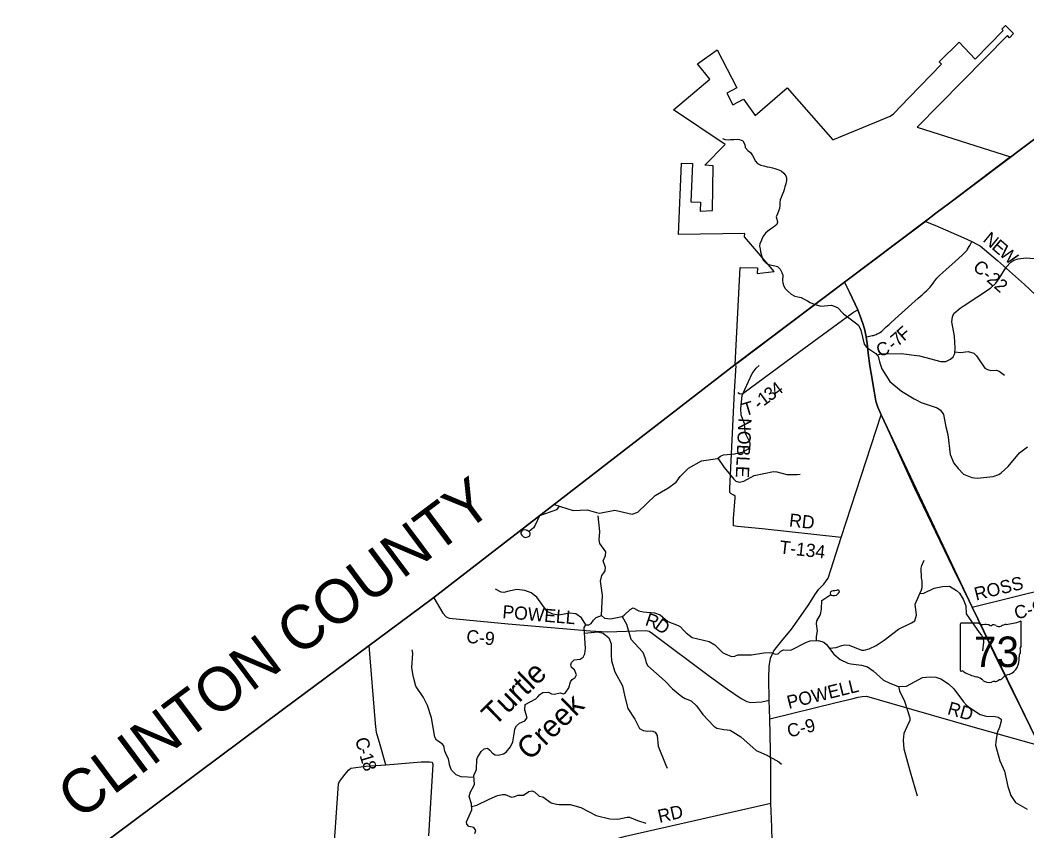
# Model space of a CAD drawing. Extents: x 1525783 to 1900577, y 218250 to 627376.
# Drawn here: x 1612574 to 1635582, y 470168 to 488683 of the extents above; entities that cross this region are included whole.
import ezdxf

# ---------------------------------------------------------------- set-up
doc = ezdxf.new("R2010")
doc.units = 0
for name, color, linetype in [('GM_X_Adjacent_County', 7, 'Continuous'), ('GM_X_Adjacent_County_Text', 7, 'Continuous'), ('GM_X_Corporation', 7, 'Continuous'), ('GM_X_County', 7, 'Continuous'), ('GM_X_County_Road', 7, 'Continuous'), ('GM_X_County_Road_Text', 7, 'Continuous'), ('GM_X_Minor_Lake', 7, 'Continuous'), ('GM_X_Minor_River', 7, 'Continuous'), ('GM_X_Minor_River_Text', 7, 'Continuous'), ('GM_X_State_Location', 7, 'Continuous'), ('GM_X_State_Route', 7, 'Continuous'), ('GM_X_State_Shield', 7, 'Continuous'), ('GM_X_Township', 7, 'Continuous'), ('GM_X_Township_Road', 7, 'Continuous'), ('GM_X_Township_Road_Text', 7, 'Continuous')]:
    doc.layers.add(name, color=color, linetype=linetype)

msp = doc.modelspace()

# ---------------------------------------------------------------- linework, layer by layer
at = {"layer": 'GM_X_Adjacent_County'}
msp.add_lwpolyline([(1655741, 500852), (1648788, 495779), (1648023, 495203), (1647133, 494533), (1640676, 489672), (1638042, 487688), (1635644, 485883), (1633819, 484508), (1633505, 484272), (1633248, 484078), (1631413, 482696), (1628958, 480847), (1628919, 480818), (1621997, 475474), (1621966, 475451), (1620523, 474378), (1618604, 472952), (1614700, 470050), (1612987, 468763), (1608261, 465210)], dxfattribs=at)
at = {"layer": 'GM_X_Corporation'}
msp.add_lwpolyline([(1627691, 485418), (1627940, 485406), (1627901, 484537), (1628121, 484528), (1628112, 484317), (1628398, 484333), (1628411, 485354), (1628219, 485374), (1628686, 485841), (1627505, 486638), (1628338, 487337), (1628054, 487687), (1628507, 488004), (1628950, 487135), (1628725, 487015), (1628861, 486748), (1629103, 486876), (1629374, 486504), (1630100, 487134), (1631145, 485950), (1632461, 486490), (1632534, 486543), (1632894, 486918), (1633630, 487680), (1633577, 487731), (1634034, 488180), (1634400, 487790), (1635040, 488449), (1635011, 488478), (1635094, 488561), (1635280, 488379), (1635185, 488282), (1635139, 488333), (1633078, 486240), (1635211, 485558), (1633823, 484511), (1633263, 484089), (1631413, 482696), (1628919, 480818), (1629029, 483037), (1629423, 483024), (1629418, 482897), (1629805, 482944), (1629128, 483732), (1629134, 483814), (1627618, 483785)], close=True, dxfattribs=at)
at = {"layer": 'GM_X_County'}
msp.add_lwpolyline([(1608261, 465210), (1612987, 468763), (1614700, 470050), (1618604, 472952), (1620523, 474378), (1621966, 475451), (1621997, 475474), (1628919, 480818), (1628958, 480847), (1631413, 482696), (1633248, 484078), (1633505, 484272), (1633819, 484508), (1635644, 485883), (1638042, 487688), (1640676, 489672), (1647133, 494533), (1648023, 495203), (1648788, 495779), (1655741, 500852)], dxfattribs=at)
at = {"layer": 'GM_X_County_Road'}
for points in [[(1633262, 484085), (1633481, 483997), (1633846, 483840), (1634145, 483711), (1634323, 483625), (1634457, 483560), (1634513, 483526), (1634612, 483448), (1634910, 483193), (1635526, 482645), (1637038, 481230)], [(1631909, 481449), (1631952, 481458), (1631982, 481464), (1632019, 481471), (1632049, 481477), (1632075, 481483), (1632095, 481490), (1632116, 481496), (1632135, 481504), (1632163, 481517), (1632185, 481528), (1632212, 481543), (1632236, 481559), (1632264, 481581), (1632308, 481621), (1632368, 481675), (1632433, 481733), (1632478, 481775), (1632724, 481995), (1632878, 482134), (1633100, 482334), (1633186, 482410), (1633244, 482463), (1633298, 482511), (1633335, 482545), (1633352, 482563), (1633372, 482583), (1633387, 482604), (1633423, 482650), (1633457, 482698), (1633480, 482731), (1633503, 482763), (1633524, 482790), (1633546, 482815), (1633574, 482841), (1633592, 482858), (1633661, 482920), (1633731, 482982), (1633942, 483174), (1634100, 483317), (1634163, 483373), (1634183, 483393), (1634201, 483413), (1634214, 483428), (1634227, 483449), (1634275, 483537), (1634323, 483625)], [(1629760, 469933), (1629755, 470250), (1629729, 470804), (1629727, 471634), (1629708, 472724), (1629696, 473150), (1629683, 473653), (1629692, 473923), (1629719, 474113), (1629799, 474283), (1629982, 474505), (1630201, 474776), (1630372, 475010), (1630601, 475336), (1630737, 475555), (1630828, 475691), (1630941, 475798), (1631037, 475940), (1631340, 476867), (1632255, 479668)], [(1634329, 475280), (1639649, 476593)], [(1622025, 475492), (1622234, 475143), (1622312, 475057), (1622379, 475023), (1623730, 474895), (1625601, 474735), (1625993, 474713), (1626875, 474747), (1626953, 474725), (1627027, 474675), (1628332, 473699), (1628737, 473407), (1629049, 473189), (1629184, 473123), (1629275, 473101), (1629528, 473114), (1629696, 473150)], [(1620932, 471674), (1620800, 472129), (1620720, 472415), (1620697, 472616), (1620552, 474399)], [(1629708, 472724), (1631227, 473103), (1631579, 473186), (1631730, 473218), (1631821, 473240), (1631913, 473241), (1632492, 473080), (1634347, 472540), (1635869, 472114)], [(1619622, 467949), (1619849, 471240), (1619871, 471298), (1620003, 471460), (1620078, 471551), (1620129, 471599), (1620473, 471642), (1620932, 471674), (1621563, 471730), (1621740, 471745), (1621848, 471748), (1621928, 471748), (1621988, 471736), (1622004, 471684), (1621903, 470055)]]:
    msp.add_lwpolyline(points, dxfattribs=at)
at = {"layer": 'GM_X_Minor_Lake'}
for points in [[(1624197, 477002), (1624160, 477024), (1624128, 477043), (1624064, 477032), (1624039, 477018), (1624015, 476980), (1624016, 476948), (1624038, 476922), (1624079, 476881), (1624127, 476870), (1624177, 476882), (1624220, 476905), (1624228, 476941)], [(1624228, 476941), (1624227, 476969), (1624222, 476980), (1624197, 477002)], [(1631109, 475550), (1631151, 475544), (1631187, 475543), (1631230, 475554), (1631278, 475598), (1631301, 475625), (1631293, 475658), (1631263, 475670), (1631231, 475658), (1631191, 475649), (1631155, 475648), (1631121, 475644), (1631095, 475629), (1631090, 475599)], [(1631090, 475599), (1631095, 475568), (1631100, 475561), (1631109, 475550)]]:
    msp.add_lwpolyline(points, dxfattribs=at)
at = {"layer": 'GM_X_Minor_River'}
for points in [[(1628625, 485978), (1628684, 485958), (1628756, 485947), (1628808, 485957), (1628882, 485960), (1628960, 485963), (1629016, 485954), (1629092, 485923), (1629133, 485840), (1629146, 485774), (1629205, 485703), (1629266, 485660)], [(1629266, 485660), (1629313, 485594), (1629339, 485539), (1629370, 485469), (1629427, 485406), (1629501, 485373), (1629568, 485352), (1629646, 485335), (1629706, 485322), (1629770, 485311), (1629824, 485297), (1629894, 485274), (1629963, 485241), (1630028, 485186), (1630070, 485131), (1630087, 485081), (1630088, 485023), (1630071, 484941), (1630054, 484877), (1630034, 484817), (1630021, 484763), (1629992, 484694), (1629965, 484632), (1629944, 484580), (1629937, 484518), (1629939, 484454), (1629928, 484384), (1629907, 484318), (1629880, 484262), (1629855, 484189), (1629870, 484136), (1629879, 484068), (1629869, 484012), (1629790, 483955), (1629721, 483910), (1629662, 483865), (1629610, 483817), (1629559, 483760), (1629532, 483702), (1629507, 483636), (1629477, 483585), (1629474, 483523), (1629485, 483458), (1629496, 483392), (1629519, 483318), (1629534, 483257), (1629558, 483203), (1629623, 483136), (1629682, 483103), (1629746, 483090), (1629822, 483073), (1629884, 483055), (1629943, 482998), (1629984, 482917), (1630001, 482861), (1630000, 482731), (1630003, 482680), (1630024, 482608), (1630057, 482554), (1630128, 482486), (1630198, 482426), (1630279, 482382), (1630345, 482362), (1630421, 482349), (1630494, 482310), (1630566, 482269), (1630631, 482238), (1630685, 482213), (1630745, 482192)], [(1632155, 481036), (1632257, 481063), (1632707, 481066), (1633127, 481014), (1633617, 480884), (1633728, 480890), (1633840, 480937), (1633897, 480996), (1633935, 481069), (1633945, 481189), (1633929, 481462), (1633870, 481793), (1633880, 481905), (1633915, 481983), (1634057, 482107), (1634124, 482152), (1634747, 482558), (1634875, 482677), (1634951, 482784), (1635109, 483041), (1635213, 483154), (1635283, 483199), (1635384, 483235), (1635567, 483257), (1635751, 483242)], [(1630745, 482192), (1630872, 482148), (1631115, 482172), (1631252, 482122), (1631393, 481972)], [(1631393, 481972), (1631667, 481773), (1631735, 481716), (1631791, 481605), (1631862, 481282), (1631927, 481205), (1632127, 481069), (1632155, 481036)], [(1633938, 481107), (1634063, 481093), (1634240, 481113), (1634367, 481077), (1634434, 481017), (1634624, 480738), (1634684, 480701), (1634755, 480684), (1634878, 480686), (1634945, 480663), (1635070, 480577)], [(1632155, 481036), (1632180, 481006), (1632216, 480882), (1632266, 480723), (1632447, 480430), (1632720, 480207), (1633004, 480036), (1633055, 480008), (1633166, 479950), (1633535, 479830), (1633606, 479779), (1633675, 479674), (1633730, 479396), (1633774, 479217), (1633828, 478766), (1633913, 478562), (1634012, 478447), (1634134, 478313), (1634325, 478238), (1634449, 478224), (1634808, 478258), (1634942, 478304), (1634995, 478343), (1635157, 478487), (1635411, 478804), (1635593, 478941)], [(1624782, 477623), (1625210, 477484), (1625536, 477499), (1625744, 477442), (1625816, 477427), (1626165, 477488), (1626564, 477399), (1626689, 477445), (1627087, 477826), (1627376, 477991), (1627568, 478135), (1627660, 478257), (1627846, 478453), (1628144, 478616), (1628510, 478675), (1628581, 478722), (1628651, 478756), (1628902, 478777), (1629097, 478824), (1629222, 478896), (1629259, 478961), (1629260, 479027), (1629173, 479199), (1629142, 479270), (1629131, 479470), (1629056, 479663), (1629042, 479810), (1629075, 480108), (1629133, 480247), (1629305, 480611), (1629393, 480731), (1629460, 480792)], [(1628517, 478680), (1628663, 478464), (1628883, 478196), (1628934, 478155), (1629006, 478132), (1629114, 478157), (1629352, 478283), (1629792, 478372), (1629868, 478369), (1630097, 478303), (1630330, 478308), (1630400, 478313)], [(1624894, 477586), (1624830, 477496), (1624440, 477359)], [(1624440, 477359), (1624346, 477147), (1624303, 477086), (1624203, 476996)], [(1625861, 475087), (1625880, 475547), (1625839, 475871), (1625867, 476000), (1625910, 476058), (1625945, 476109), (1625952, 476181), (1625901, 476338), (1625949, 476460), (1625962, 476539), (1625823, 476728), (1625808, 476818), (1625825, 477004), (1625784, 477361)], [(1631068, 474338), (1631221, 474357), (1631350, 474399), (1631412, 474414), (1631518, 474412), (1631806, 474296), (1631864, 474293), (1631981, 474323), (1632134, 474399), (1632322, 474524), (1632649, 474775), (1632947, 474915), (1633022, 474962), (1633062, 475097), (1633032, 475346), (1633173, 475672), (1633190, 475728), (1633190, 475868), (1633176, 475945), (1633165, 476169), (1633178, 476231), (1633236, 476352)], [(1625503, 474874), (1625400, 475032), (1625271, 475122), (1625127, 475139), (1624882, 475094), (1624750, 475116), (1624615, 475177), (1624386, 475505), (1624255, 475605), (1624110, 475659), (1623922, 475678), (1623744, 475641), (1623627, 475611), (1623567, 475618), (1623440, 475690)], [(1633136, 475586), (1633226, 475597), (1633466, 475708), (1633653, 475751), (1633815, 475753), (1633976, 475660), (1634045, 475599), (1634127, 475463), (1634187, 475308), (1634198, 475122), (1634491, 474695), (1634542, 474640), (1634583, 474559), (1634594, 474477), (1634571, 474279)], [(1630772, 474516), (1630772, 474604), (1630798, 474738), (1630771, 474895), (1630782, 474965), (1630868, 475109), (1630890, 475231), (1630895, 475425), (1631098, 475564)], [(1625444, 474138), (1625479, 474212), (1625493, 474334), (1625468, 474811), (1625503, 474874), (1625571, 474875), (1625626, 474903), (1625677, 474982), (1625742, 475039), (1625861, 475087), (1625932, 475022), (1626068, 475012), (1626331, 475066), (1626382, 475093), (1626516, 475227), (1626586, 475260), (1626710, 475196), (1626813, 475168), (1627069, 475150), (1627205, 475100), (1627378, 474949), (1627613, 474856), (1627665, 474827), (1627726, 474756), (1627799, 474687), (1627931, 474582), (1628322, 474496), (1628451, 474420), (1628626, 474241), (1628688, 474210), (1628833, 474150), (1628905, 474155), (1628976, 474186), (1629286, 474191), (1629573, 474236), (1629697, 474240), (1629753, 474232), (1629831, 474206), (1629899, 474207), (1629958, 474268), (1630021, 474302), (1630191, 474297), (1630544, 474480), (1630628, 474504), (1630819, 474519), (1630944, 474475), (1631004, 474422), (1631168, 474206), (1631315, 474085), (1631487, 473998), (1631561, 473979), (1631805, 473951), (1631936, 473913), (1632067, 473821), (1632304, 473609), (1632433, 473547), (1632642, 473464), (1632832, 473469), (1633200, 473673), (1633380, 473689), (1633504, 473677), (1633618, 473639), (1633788, 473524), (1633914, 473408), (1634134, 473112), (1634205, 473041), (1634272, 472984), (1634512, 472828), (1634649, 472790), (1634856, 472781), (1634923, 472764), (1634993, 472720), (1634998, 472670), (1634960, 472535), (1634904, 472403), (1634870, 472202), (1634867, 472126), (1634964, 471768), (1635039, 471602), (1635068, 471532), (1635149, 471178), (1635217, 470977), (1635325, 470817), (1635535, 470691), (1635587, 470661)], [(1626331, 475066), (1626428, 474886), (1626529, 474548), (1626807, 474251), (1626861, 474108), (1626883, 474004), (1626918, 473937), (1627315, 473585), (1627486, 473410), (1627696, 473238), (1627769, 473191), (1627910, 473139), (1628035, 473023), (1628174, 472822), (1628428, 472556), (1628497, 472513), (1628653, 472482), (1628735, 472475), (1628799, 472464), (1629042, 472312), (1629398, 472006), (1629625, 471901), (1629910, 471748), (1629974, 471693)], [(1625475, 474686), (1625779, 474712), (1625895, 474680), (1626025, 474578), (1626083, 474439), (1626083, 474185), (1626091, 474048), (1626163, 473803), (1626340, 473480), (1626396, 473226), (1626460, 472961), (1626619, 472722), (1626731, 472508), (1626813, 472457), (1626919, 472447), (1626969, 472450), (1627037, 472447), (1627090, 472423), (1627133, 472348), (1627157, 472099), (1627333, 471666), (1627358, 471599)], [(1622948, 471385), (1622656, 471400), (1622538, 471446), (1622434, 471554), (1622394, 471655), (1622360, 471815), (1622325, 471882), (1622277, 471989), (1622257, 472107), (1622217, 472158), (1622092, 472236), (1622049, 472305), (1621974, 472747), (1621887, 473032), (1621791, 473210), (1621619, 473469), (1621572, 473648), (1621557, 473718), (1621522, 473893), (1621547, 474229), (1621536, 474299)], [(1622966, 470110), (1622989, 470173), (1622942, 470244), (1622832, 470264), (1622779, 470319), (1622778, 470371), (1622898, 470649), (1622886, 470782), (1622837, 470953), (1622867, 471058), (1622935, 471180), (1622960, 471237), (1622945, 471432), (1623007, 471571), (1623010, 471795), (1623025, 471847), (1623111, 471982), (1623180, 472043), (1623253, 472054), (1623310, 472009), (1623367, 471944), (1623427, 471907), (1623502, 471896), (1623621, 471926), (1623682, 471963), (1623782, 472088), (1623836, 472201), (1623869, 472431), (1623880, 472501), (1623918, 472570), (1623986, 472625), (1624105, 472679), (1624163, 472747), (1624111, 472928), (1624119, 473052), (1624356, 473182), (1624406, 473225), (1624451, 473281), (1624522, 473328), (1624646, 473336), (1624716, 473299), (1624786, 473292), (1624916, 473320), (1624982, 473296), (1625032, 473310), (1625112, 473437), (1625150, 473568), (1625191, 473628), (1625262, 473667), (1625291, 473734), (1625243, 473849), (1625178, 473902), (1625159, 473963), (1625177, 474014), (1625238, 474074), (1625373, 474091), (1625444, 474138)], [(1632648, 473464), (1632669, 473369), (1632783, 473129), (1632909, 472749), (1632904, 472689), (1632836, 472546), (1632773, 472388), (1632753, 472241), (1632768, 472038), (1632914, 471517), (1633073, 470970)], [(1622891, 470727), (1623010, 470758), (1623290, 470892), (1623482, 470973), (1623598, 471001), (1623658, 470996), (1623806, 470936), (1623876, 470951), (1623949, 470982), (1624075, 470982), (1624198, 471064), (1624268, 471083), (1624326, 471058), (1624437, 470964), (1624519, 470947), (1624711, 470807), (1624830, 470776), (1624892, 470773), (1625142, 470771), (1625388, 470705), (1625739, 470515), (1626052, 470444), (1626234, 470433), (1626449, 470484), (1626501, 470481), (1626682, 470408), (1626871, 470347)]]:
    msp.add_lwpolyline(points, dxfattribs=at)
at = {"layer": 'GM_X_State_Route'}
msp.add_lwpolyline([(1631416, 482697), (1631527, 482470), (1631715, 482066), (1631797, 481863), (1631841, 481732), (1631877, 481600), (1631909, 481449), (1631941, 481246), (1631957, 481078), (1631994, 480786), (1632021, 480610), (1632091, 480207), (1632131, 479980), (1632176, 479841), (1632255, 479668), (1633016, 477997), (1633882, 476188), (1634329, 475280), (1634827, 474223), (1635799, 472256)], dxfattribs=at)
at = {"layer": 'GM_X_State_Shield'}
for p, q in [((1634060, 474892), (1634060, 473836)), ((1634482, 474910), (1634074, 474910)), ((1635452, 474384), (1635452, 474937)), ((1635452, 474384), (1635452, 474384))]:
    msp.add_line(p, q, dxfattribs=at)
for centre, radius, start, end in [((1634076, 474894), 16.1, 98.1301, 188.1301), ((1634579, 475033), 156, 231.6195, 271.1119), ((1634956, 476351), 1476, 275.8445, 288.9065), ((1635437, 474939), 15.5, 351.8621, 97.738), ((1634631, 474317), 562, 80.4867, 94.9883), ((1634758, 474900), 45.1, 219.7921, 297.1024), ((1634824, 474778), 93.8, 54.4667, 119.1411), ((1634945, 474945), 113, 233.8562, 294.8282), ((1635145, 474588), 297, 97.3462, 120.7689), ((1635508, 474153), 105, 136.8065, 186.9296), ((1635449, 474343), 24, 107.944, 210.337), ((1635296, 474273), 144, 340.033, 23.6496), ((1635436, 474382), 16.6, 289.6038, 7.7341), ((1635039, 474082), 369, 292.3089, 8.9858), ((1634076, 473833), 16.3, 171.9584, 258.3066), ((1634079, 473941), 124, 267.339, 280.6039), ((1634104, 473775), 44.8, 29.7484, 93.2717), ((1634669, 474724), 1066, 240.4129, 257.1985), ((1635195, 473539), 202, 94.4031, 142.5768), ((1634352, 473361), 334, 47.1842, 75.836), ((1634712, 473769), 212, 230.7004, 286.2918), ((1634835, 473404), 174, 85.6951, 111.2099), ((1634850, 473690), 113, 268.777, 315.5493), ((1634952, 473588), 31.8, 65.7517, 132.6484), ((1634939, 473733), 119, 282.8732, 323.2771)]:
    msp.add_arc(centre, radius, start, end, dxfattribs=at)
at = {"layer": 'GM_X_Township'}
for points in [[(1635799, 472256), (1634329, 475280), (1632255, 479668), (1632176, 479841), (1632131, 479980), (1632091, 480207), (1632021, 480610), (1631994, 480786), (1631957, 481078), (1631941, 481246), (1631909, 481449), (1631877, 481600), (1631841, 481732), (1631797, 481863), (1631715, 482066), (1631527, 482470), (1631413, 482696), (1633248, 484078), (1633505, 484272), (1633819, 484508), (1635644, 485883)], [(1614700, 470050), (1618604, 472952), (1620523, 474378), (1621966, 475451), (1621997, 475474), (1628919, 480818), (1628958, 480847), (1631413, 482696), (1631527, 482470), (1631715, 482066), (1631797, 481863), (1631841, 481732), (1631877, 481600), (1631909, 481449), (1631941, 481246), (1631957, 481078), (1631994, 480786), (1632021, 480610), (1632091, 480207), (1632131, 479980), (1632176, 479841), (1632255, 479668), (1634329, 475280), (1635799, 472256)]]:
    msp.add_lwpolyline(points, dxfattribs=at)
at = {"layer": 'GM_X_Township_Road'}
for points in [[(1628974, 480181), (1629013, 480158), (1629041, 480145), (1629093, 480154), (1629122, 480177), (1630370, 481102), (1631365, 481834), (1631618, 482014), (1631715, 482066)], [(1631340, 476867), (1629534, 477066), (1628967, 477121), (1628875, 477133), (1628880, 477304), (1628912, 477772), (1628915, 477808), (1628888, 477838), (1628852, 477847), (1628824, 477866), (1628795, 477899), (1628796, 477987), (1628900, 480201), (1628935, 480798)], [(1625986, 467115), (1626191, 469948), (1626218, 469993), (1626412, 470050), (1629729, 470804)]]:
    msp.add_lwpolyline(points, dxfattribs=at)

# ---------------------------------------------------------------- texts
at = {"layer": 'GM_X_Adjacent_County_Text'}
msp.add_text('CLINTON COUNTY', height=1000, rotation=36.7477, dxfattribs=at).set_placement((1613923, 470392))
at = {"layer": 'GM_X_County_Road_Text'}
for s, rotation, p in [('N', 320.6063, (1634557, 483641)), ('E', 319.3587, (1634759, 483474)), ('W', 319.2433, (1634929, 483328)), ('C-22', 318.8459, (1634326, 483010)), ('7', 41.4332, (1632631, 481215)), ('F', 41.6376, (1632770, 481338)), ('C', 21.3477, (1632211, 480985)), ('-', 40.756, (1632535, 481132)), ('ROSS', 13.9025, (1634421, 475425)), ('C-92', 13.8701, (1635335, 474994)), ('POWELL', 355.1129, (1623587, 475027)), ('R', 341.4182, (1626838, 474870)), ('D', 324.2464, (1627051, 474802)), ('C-9', 354.4738, (1622761, 474466)), ('POWELL', 13.8309, (1630140, 472952)), ('RD', 344.0556, (1633747, 472837)), ('C-9', 13.9242, (1630144, 472297)), ('C', 285.2688, (1620226, 472259)), ('1', 286.7937, (1620328, 471894)), ('-', 286.2693, (1620293, 472015)), ('8', 287.0448, (1620382, 471716))]:
    msp.add_text(s, height=300, rotation=rotation, dxfattribs=at).set_placement(p)
at = {"layer": 'GM_X_Minor_River_Text'}
for s, rotation, p in [('Turtle', 44.1863, (1623417, 472539)), ('Creek', 43.9898, (1624219, 471754))]:
    msp.add_text(s, height=500, rotation=rotation, dxfattribs=at).set_placement(p)
at = {"layer": 'GM_X_State_Location'}
msp.add_text('73', height=1, rotation=0, dxfattribs=at).set_placement((1634489, 474221))
for s in ['s', 'r']:
    msp.add_text(s, height=1, dxfattribs=at).set_placement((1634741, 474294))
at = {"layer": 'GM_X_State_Shield'}
msp.add_text('73', height=696.1, dxfattribs=at).set_placement((1634369, 473910))
at = {"layer": 'GM_X_Township_Road_Text'}
for s, rotation, p in [('4', 36.4015, (1629862, 480076)), ('1', 36.5389, (1629565, 479857)), ('3', 36.4276, (1629713, 479967)), ('T', 16.8979, (1629137, 479635)), ('-', 43.9869, (1629484, 479778)), ('NOBLE', 267.3225, (1628992, 479599)), ('RD', 353.5502, (1630137, 477122)), ('T-134', 353.5362, (1629916, 476505)), ('RD', 12.9561, (1627185, 470348))]:
    msp.add_text(s, height=300, rotation=rotation, dxfattribs=at).set_placement(p)

doc.saveas('drawing.dxf')
